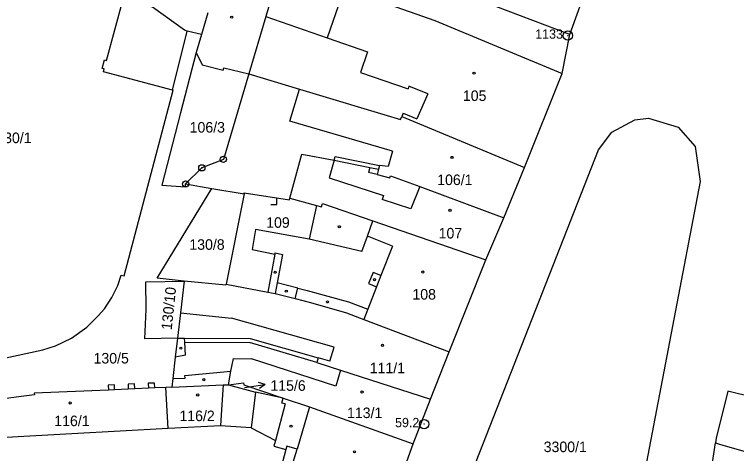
# Model space of a CAD drawing. Extents: x -733394 to -722299, y -1082822 to -1075049.
# Drawn here: x -728366.4 to -728250, y -1079152.8 to -1079081.9 of the extents above; entities that cross this region are included whole.
import ezdxf

# ---------------------------------------------------------------- set-up
doc = ezdxf.new("R2010")
doc.units = 0
for name, color, linetype in [('Hranice parcel', 7, 'Continuous'), ('Parcelní čísla', 7, 'Continuous'), ('Pop  PČ popisy', 7, 'Continuous'), ('Vnitřní kresba', 7, 'Continuous'), ('Značky bodu BP', 7, 'Continuous'), ('Značky budov', 7, 'Continuous'), ('Značky kultur', 7, 'Continuous')]:
    doc.layers.add(name, color=color, linetype=linetype)

msp = doc.modelspace()

# ---------------------------------------------------------------- linework, layer by layer
at = {"layer": 'Hranice parcel'}
for p, q in [((-728276.9, -1079085.1), (-728270.85, -1079068.49)), ((-728335.21, -1079081.62), (-728336.26, -1079085.14)), ((-728336.26, -1079085.14), (-728338.56, -1079084.56)), ((-728336.26, -1079085.14), (-728337.11, -1079088.04)), ((-728278.09, -1079091.44), (-728276.9, -1079085.1)), ((-728284.2, -1079106.59), (-728278.09, -1079091.44)), ((-728287.5, -1079114.73), (-728284.2, -1079106.59)), ((-728338.8, -1079109.23), (-728334.6, -1079109.95)), ((-728334.6, -1079109.95), (-728329.37, -1079110.85)), ((-728329.37, -1079110.85), (-728332.29, -1079125.42)), ((-728322, -1079111.56), (-728317.71, -1079112.72)), ((-728290.42, -1079121.48), (-728287.5, -1079114.73)), ((-728296.33, -1079136.31), (-728290.42, -1079121.48)), ((-728332.29, -1079125.42), (-728325.54, -1079126.69)), ((-728299.35, -1079144), (-728296.33, -1079136.31)), ((-728341.01, -1079142.05), (-728341.98, -1079142.09)), ((-728341.62, -1079148.72), (-728341.98, -1079142.09)), ((-728331.89, -1079141.64), (-728327.53, -1079142.82)), ((-728327.53, -1079142.82), (-728328.25, -1079148.59)), ((-728323.08, -1079143.79), (-728327.53, -1079142.82)), ((-728302.13, -1079151.16), (-728299.35, -1079144)), ((-728305.63, -1079161.11), (-728302.13, -1079151.16)), ((-728254.06, -1079155.27), (-728253.41, -1079151.03))]:
    msp.add_line(p, q, dxfattribs=at)
for points in [[(-728338.56, -1079084.56), (-728338.96, -1079084.44), (-728344.13, -1079080.71), (-728348.89, -1079079.39), (-728367.36, -1079074.56), (-728367.43, -1079074.85), (-728378.1, -1079072.07), (-728380.48, -1079071.44), (-728388.58, -1079087.22), (-728400.43, -1079110.31)], [(-728332.54, -1079072.51), (-728323.65, -1079074.72), (-728316.85, -1079076.45), (-728313.22, -1079077.72), (-728298.64, -1079082.85), (-728278.09, -1079091.44)], [(-728276.9, -1079085.1), (-728290.77, -1079079.85), (-728291.16, -1079079.71)], [(-728373.22, -1079138.48), (-728370.57, -1079137.91), (-728361.83, -1079136.04), (-728359.76, -1079135.39), (-728357.17, -1079134.12), (-728354.71, -1079132.35), (-728352.89, -1079130.54), (-728351.87, -1079129.41), (-728350.69, -1079127.56), (-728349.74, -1079125.63), (-728349.17, -1079123.97), (-728348.71, -1079124.08), (-728340.83, -1079094.11), (-728340.93, -1079094.08), (-728338.56, -1079084.56)], [(-728337.11, -1079088.04), (-728339.61, -1079097.77), (-728342.62, -1079109.45), (-728338.83, -1079109.72), (-728338.8, -1079109.23)], [(-728337.11, -1079088.04), (-728336.11, -1079090.02), (-728332.74, -1079090.89), (-728332.66, -1079090.5), (-728328.6, -1079091.48)], [(-728328.6, -1079091.48), (-728332.72, -1079105.28), (-728336.19, -1079106.64), (-728338.8, -1079109.23)], [(-728328.6, -1079091.48), (-728320.47, -1079093.93), (-728304.16, -1079098.85), (-728303.95, -1079098.35), (-728284.2, -1079106.59)], [(-728322, -1079111.56), (-728320.07, -1079104.44), (-728314.86, -1079105.42), (-728309.12, -1079106.57), (-728307.72, -1079106.85), (-728307.93, -1079107.73), (-728305.89, -1079108.23), (-728305.79, -1079107.94), (-728301.05, -1079109.63), (-728287.5, -1079114.73)], [(-728339.06, -1079124.91), (-728343.41, -1079124.43), (-728334.6, -1079109.95)], [(-728329.37, -1079110.85), (-728329.34, -1079110.7), (-728322.07, -1079111.79), (-728322, -1079111.56)], [(-728317.71, -1079112.72), (-728318.89, -1079118.14), (-728327.56, -1079116.6), (-728328.07, -1079119.83), (-728324.4, -1079120.58), (-728325.54, -1079126.69)], [(-728317.71, -1079112.72), (-728316.9, -1079112.94), (-728316.75, -1079112.41), (-728308.64, -1079115.21), (-728290.42, -1079121.48)], [(-728340.11, -1079134.13), (-728345.38, -1079134.22), (-728345.16, -1079129.5), (-728345.2, -1079125.05), (-728339.06, -1079124.91)], [(-728339.06, -1079124.91), (-728339.65, -1079130.06), (-728340.11, -1079134.13)], [(-728332.29, -1079125.42), (-728332.32, -1079125.57), (-728339.06, -1079124.91)], [(-728325.54, -1079126.69), (-728324.38, -1079126.91), (-728321.16, -1079127.75), (-728318.7, -1079128.38), (-728312.86, -1079130.04), (-728310.06, -1079131.1), (-728296.33, -1079136.31)], [(-728340.11, -1079134.13), (-728340.46, -1079137.2), (-728340.85, -1079140.66), (-728341.01, -1079142.05)], [(-728340.11, -1079134.13), (-728338.98, -1079134.14), (-728328.39, -1079134.19), (-728317.45, -1079137.28), (-728317.68, -1079138.07), (-728313.85, -1079139.28), (-728299.35, -1079144)], [(-728341.98, -1079142.09), (-728343.78, -1079142.16), (-728343.82, -1079141.37), (-728344.85, -1079141.41), (-728344.81, -1079142.21), (-728347, -1079142.31), (-728347.03, -1079141.51), (-728348.07, -1079141.55), (-728348.04, -1079142.35), (-728350.24, -1079142.45), (-728350.28, -1079141.65), (-728351.29, -1079141.7), (-728351.25, -1079142.5), (-728363.21, -1079143.03), (-728363.18, -1079143.28), (-728365.31, -1079143.56), (-728368.45, -1079143.98)], [(-728331.89, -1079141.64), (-728329.48, -1079141.36), (-728329.42, -1079141.68), (-728323.08, -1079143.79)], [(-728341.01, -1079142.05), (-728332.76, -1079141.68), (-728331.89, -1079141.64)], [(-728239.2, -1079145.68), (-728251.39, -1079142.66), (-728253.28, -1079150.26), (-728253.41, -1079151.03)], [(-728323.08, -1079143.79), (-728318.82, -1079145.21), (-728302.13, -1079151.16)], [(-728328.25, -1079148.59), (-728333.2, -1079148.26), (-728341.62, -1079148.72)], [(-728341.62, -1079148.72), (-728364.89, -1079149.99), (-728371.26, -1079150.4)], [(-728328.25, -1079148.59), (-728324.31, -1079150.62), (-728324.56, -1079151.56), (-728322.64, -1079152.12), (-728323.48, -1079155.14), (-728323.65, -1079155.74)], [(-728253.41, -1079151.03), (-728252.62, -1079151.31), (-728232.95, -1079156.87), (-728228.13, -1079158.28)]]:
    msp.add_lwpolyline(points, dxfattribs=at)
at = {"layer": 'Pop  PČ popisy'}
for p, q in [((-728325.98, -1079141.63), (-728327.04, -1079141.28)), ((-728329.31, -1079142.1), (-728328.95, -1079142.05)), ((-728328.95, -1079142.05), (-728325.98, -1079141.63)), ((-728325.98, -1079141.63), (-728326.9, -1079142.27))]:
    msp.add_line(p, q, dxfattribs=at)
at = {"layer": 'Vnitřní kresba'}
for p, q in [((-728323.65, -1079074.72), (-728325.86, -1079082.2)), ((-728313.22, -1079077.72), (-728315.98, -1079085.64)), ((-728351.58, -1079089.3), (-728348.89, -1079079.39)), ((-728325.86, -1079082.2), (-728328.6, -1079091.48)), ((-728325.86, -1079082.2), (-728315.98, -1079085.64)), ((-728315.98, -1079085.64), (-728309.47, -1079087.91)), ((-728309.47, -1079087.91), (-728310.6, -1079091.27)), ((-728352.23, -1079090.61), (-728351.87, -1079089.22)), ((-728351.87, -1079089.22), (-728351.58, -1079089.3)), ((-728351.94, -1079090.68), (-728352.23, -1079090.61)), ((-728352.05, -1079091.14), (-728351.94, -1079090.68)), ((-728340.93, -1079094.08), (-728352.05, -1079091.14)), ((-728310.6, -1079091.27), (-728302.96, -1079093.9)), ((-728302.8, -1079093.48), (-728302.96, -1079093.9)), ((-728299.78, -1079094.71), (-728302.8, -1079093.48)), ((-728321.99, -1079099.1), (-728320.47, -1079093.93)), ((-728299.78, -1079094.71), (-728301.53, -1079098.73)), ((-728303.73, -1079097.82), (-728303.95, -1079098.35)), ((-728303.73, -1079097.82), (-728301.53, -1079098.73)), ((-728305.45, -1079103.96), (-728321.99, -1079099.1)), ((-728270.09, -1079100.88), (-728266.4, -1079098.89)), ((-728266.4, -1079098.89), (-728264.19, -1079098.64)), ((-728264.19, -1079098.64), (-728259.42, -1079100.09)), ((-728259.42, -1079100.09), (-728256.68, -1079103.21)), ((-728272.26, -1079103.75), (-728270.09, -1079100.88)), ((-728305.45, -1079103.96), (-728306.16, -1079106.41)), ((-728301.68, -1079178.82), (-728272.26, -1079103.75)), ((-728256.68, -1079103.21), (-728255.85, -1079108.84)), ((-728314.86, -1079105.42), (-728315.65, -1079108.23)), ((-728314.86, -1079105.42), (-728314.69, -1079104.81)), ((-728314.69, -1079104.81), (-728307.57, -1079106.24)), ((-728309.12, -1079106.57), (-728309.32, -1079107.4)), ((-728307.57, -1079106.24), (-728307.72, -1079106.85)), ((-728306.16, -1079106.41), (-728307.57, -1079106.24)), ((-728307.93, -1079107.73), (-728309.32, -1079107.4)), ((-728315.65, -1079108.23), (-728306.93, -1079111.09)), ((-728255.85, -1079108.84), (-728270.5, -1079185.18)), ((-728301.05, -1079109.63), (-728302.52, -1079113.26)), ((-728306.93, -1079111.09), (-728307.14, -1079111.75)), ((-728302.52, -1079113.26), (-728307.14, -1079111.75)), ((-728309.5, -1079117.65), (-728308.64, -1079115.21)), ((-728310.38, -1079120.14), (-728318.89, -1079118.14)), ((-728310.38, -1079120.14), (-728309.5, -1079117.65)), ((-728305.48, -1079119.26), (-728309.5, -1079117.65)), ((-728305.48, -1079119.26), (-728307.32, -1079124.03)), ((-728324.4, -1079120.58), (-728324.36, -1079120.37)), ((-728324.36, -1079120.37), (-728323.2, -1079120.61)), ((-728323.2, -1079120.61), (-728324.06, -1079125.2)), ((-728308.6, -1079123.53), (-728309.31, -1079125.32)), ((-728307.32, -1079124.03), (-728308.6, -1079123.53)), ((-728307.32, -1079124.03), (-728308.02, -1079125.82)), ((-728324.06, -1079125.2), (-728324.38, -1079126.91)), ((-728320.72, -1079126.04), (-728324.06, -1079125.2)), ((-728321.16, -1079127.75), (-728320.72, -1079126.04)), ((-728320.72, -1079126.04), (-728319.2, -1079126.43)), ((-728308.02, -1079125.82), (-728309.42, -1079129.45)), ((-728309.31, -1079125.32), (-728308.02, -1079125.82)), ((-728319.2, -1079126.43), (-728312.56, -1079128.26)), ((-728312.56, -1079128.26), (-728309.42, -1079129.45)), ((-728309.42, -1079129.45), (-728310.06, -1079131.1)), ((-728339.65, -1079130.06), (-728331.43, -1079130.89)), ((-728314.86, -1079135.57), (-728331.43, -1079130.89)), ((-728338.95, -1079134.76), (-728338.98, -1079134.14)), ((-728338.83, -1079136.88), (-728338.95, -1079134.76)), ((-728338.95, -1079134.76), (-728328.5, -1079134.84)), ((-728317.68, -1079138.07), (-728328.5, -1079134.84)), ((-728315.56, -1079137.86), (-728314.86, -1079135.57)), ((-728338.83, -1079136.88), (-728340.46, -1079137.2)), ((-728331.49, -1079139.48), (-728331.11, -1079137.41)), ((-728331.11, -1079137.41), (-728328.18, -1079137.46)), ((-728314.59, -1079141.86), (-728328.18, -1079137.46)), ((-728315.56, -1079137.86), (-728317.45, -1079137.28)), ((-728338.92, -1079140.18), (-728331.49, -1079139.48)), ((-728338.9, -1079140.58), (-728338.92, -1079140.18)), ((-728331.89, -1079141.64), (-728331.49, -1079139.48)), ((-728313.85, -1079139.28), (-728314.59, -1079141.86)), ((-728340.85, -1079140.66), (-728338.9, -1079140.58)), ((-728350.24, -1079142.45), (-728351.25, -1079142.5)), ((-728347, -1079142.31), (-728348.04, -1079142.35)), ((-728343.78, -1079142.16), (-728344.81, -1079142.21)), ((-728332.76, -1079141.68), (-728333.08, -1079146.49)), ((-728323.31, -1079144.61), (-728323.08, -1079143.79)), ((-728322.76, -1079144.75), (-728324.31, -1079150.62)), ((-728322.76, -1079144.75), (-728323.31, -1079144.61)), ((-728318.82, -1079145.21), (-728320.83, -1079152.03)), ((-728333.08, -1079146.49), (-728333.2, -1079148.26)), ((-728322.47, -1079151.55), (-728322.64, -1079152.12)), ((-728320.83, -1079152.03), (-728322.47, -1079151.55)), ((-728322.08, -1079156.2), (-728320.83, -1079152.03))]:
    msp.add_line(p, q, dxfattribs=at)
at = {"layer": 'Značky bodu BP'}
for centre, radius in [((-728277.2, -1079085.3), 0.75), ((-728277.2, -1079085.3), 0.03), ((-728332.72, -1079105.28), 0.5), ((-728332.72, -1079105.28), 0.0303), ((-728336.19, -1079106.64), 0.5), ((-728336.19, -1079106.64), 0.0303), ((-728338.8, -1079109.23), 0.5), ((-728338.8, -1079109.23), 0.0303), ((-728300.36, -1079148), 0.75), ((-728300.36, -1079148), 0.03)]:
    msp.add_circle(centre, radius, dxfattribs=at)
at = {"layer": 'Značky budov'}
for centre in [(-728331.37, -1079082.32), (-728292.32, -1079091.36), (-728295.88, -1079104.96), (-728296.18, -1079113.49), (-728314.03, -1079116.15), (-728324.37, -1079123.49), (-728300.56, -1079123.46), (-728308.37, -1079124.7), (-728322.58, -1079126.55), (-728315.93, -1079128.28), (-728339.57, -1079135.75), (-728307.08, -1079135.3), (-728335.87, -1079140.83), (-728310.36, -1079142.83), (-728336.86, -1079143.3), (-728357.4, -1079144.59), (-728321.83, -1079148.34), (-728311.58, -1079152.47)]:
    msp.add_circle(centre, 0.175, dxfattribs=at)
at = {"layer": 'Značky kultur'}
for p, q in [((-728324.08, -1079112.58), (-728324.08, -1079111.58)), ((-728325.08, -1079112.58), (-728324.08, -1079112.58))]:
    msp.add_line(p, q, dxfattribs=at)

# ---------------------------------------------------------------- texts
at = {"layer": 'Parcelní čísla'}
for s, p in [('105', (-728294.11, -1079095.85)), ('106/3', (-728338.15, -1079100.95)), ('130/1', (-728369.32, -1079102.65)), ('106/1', (-728298.25, -1079109.42)), ('109', (-728325.82, -1079116.32)), ('107', (-728298.02, -1079118.04)), ('130/8', (-728338.2, -1079119.87)), ('108', (-728302.25, -1079127.9)), ('130/5', (-728353.64, -1079138.22)), ('111/1', (-728309.13, -1079139.8)), ('115/6', (-728325.14, -1079142.63)), ('116/2', (-728339.8, -1079147.52)), ('113/1', (-728312.79, -1079147.03)), ('116/1', (-728359.97, -1079148.33)), ('3300/1', (-728281.09, -1079152.52))]:
    msp.add_text(s, height=1.7, dxfattribs=at).set_placement(p)
msp.add_text('130/10', height=1.7, rotation=84, dxfattribs=at).set_placement((-728341.05, -1079132.88))
at = {"layer": 'Značky bodu BP'}
for s, p in [('1133', (-728282.45, -1079085.8)), ('59.2', (-728305.04, -1079148.5))]:
    msp.add_text(s, height=1.5, dxfattribs=at).set_placement(p)

doc.saveas('drawing.dxf')
